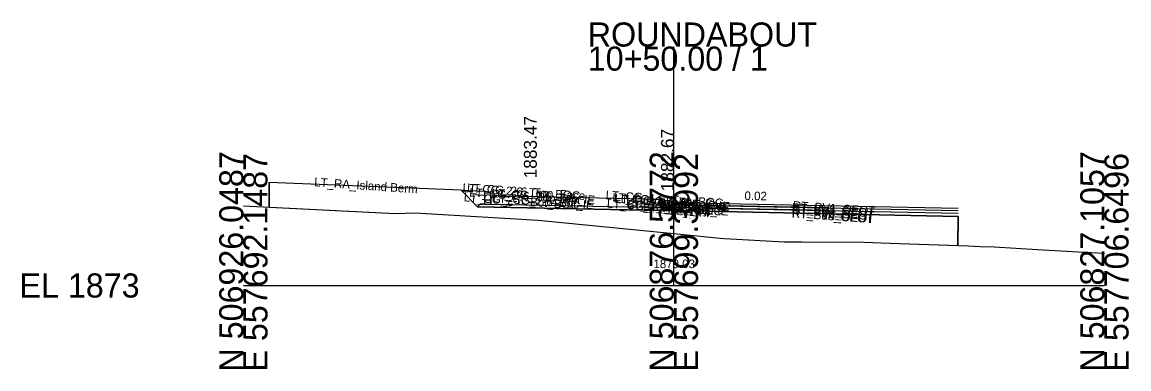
# Model space of a CAD drawing. Extents: x -36 to 140, y -10 to 2515.
# Drawn here: x -35.7 to 92.8, y 490.3 to 530.6 of the extents above; entities that cross this region are included whole.
import ezdxf

# ---------------------------------------------------------------- set-up
doc = ezdxf.new("R2010")
doc.units = 0
for name, color, linetype in [('Default', 7, 'Continuous'), ('Exist Cross Section Cell', 7, 'Continuous'), ('Exist XS Center Line Elevation Label', 7, 'Continuous'), ('Exist XS Ground Line', 7, 'Continuous'), ('Prop CMT Conc Surface', 7, 'Continuous'), ('Prop CMT Pvmt Course 1', 7, 'Continuous'), ('Prop CMT Pvmt Course 2', 7, 'Continuous'), ('Prop CMT Pvmt Course 3', 7, 'Continuous'), ('Prop CMT Pvmt Course 4', 7, 'Continuous'), ('Prop CMT Slope Grass', 7, 'Continuous'), ('Prop CMT Subgrade Earthwork', 7, 'Continuous'), ('Prop Conc 4in Sidewalk', 7, 'Continuous'), ('Prop XS Earthwork Shape', 7, 'Continuous'), ('Prop XS Finish Grade Earthwork', 7, 'Continuous'), ('Prop XS Hydro Elevations', 7, 'Continuous'), ('Typical Structure Recommendation Sheet 1 CELL', 7, 'Continuous')]:
    doc.layers.add(name, color=color, linetype=linetype)

msp = doc.modelspace()

# ---------------------------------------------------------------- linework, layer by layer
at = {"layer": 'Exist Cross Section Cell'}
for p, q in [((40, 500), (40, 527.77)), ((-10, 500), (40, 500)), ((40, 500), (90, 500))]:
    msp.add_line(p, q, dxfattribs=at)
at = {"layer": 'Exist XS Ground Line'}
msp.add_line((86.97, 503.93), (89.99, 503.75), dxfattribs=at)
msp.add_lwpolyline([(-10, 509.26), (7.68, 508.38), (9.93, 508.44), (24.23, 507.6), (40, 506.03), (45.36, 505.5), (45.89, 505.46), (52.81, 505.08), (54.85, 505.08), (62.09, 505.04), (65.08, 504.92), (74.19, 504.6), (75.57, 504.54), (77.2, 504.49), (82.21, 504.19), (86.97, 503.93), (90, 503.75)], dxfattribs=at)
at = {"layer": 'Prop CMT Conc Surface'}
for p, q in [((18.65, 510.75), (18, 510.96)), ((18, 510.96), (18, 509.96)), ((18.75, 509.96), (18.75, 510.61)), ((17.2, 509.16), (17.5, 509.46)), ((18, 509.46), (17.5, 509.46)), ((18, 509.96), (18.75, 509.96)), ((18, 509.96), (18, 509.46)), ((18, 509.46), (18.75, 509.46)), ((18.75, 509.46), (18.75, 509.96)), ((38.5, 509.05), (38.5, 510.05)), ((39.19, 509.82), (38.5, 510.05)), ((40, 509.05), (38.5, 509.05)), ((38.59, 509.26), (38.52, 509.25)), ((38.52, 509.25), (38.55, 509.14)), ((38.55, 509.14), (38.59, 509.26)), ((38.65, 509.88), (38.56, 509.88)), ((38.56, 509.88), (38.64, 509.79)), ((38.64, 509.79), (38.65, 509.88)), ((38.85, 509.58), (38.89, 509.43)), ((38.93, 509.52), (38.85, 509.58)), ((38.89, 509.43), (38.93, 509.52)), ((39.15, 509.29), (39.24, 509.24)), ((39.18, 509.16), (39.15, 509.29)), ((39.24, 509.24), (39.18, 509.16)), ((39.25, 509.73), (39.25, 509.73)), ((40, 509.64), (39.34, 509.64)), ((39.51, 509.25), (39.44, 509.23)), ((39.44, 509.23), (39.47, 509.12)), ((39.47, 509.12), (39.51, 509.25)), ((39.76, 509.56), (39.81, 509.41)), ((39.85, 509.5), (39.76, 509.56)), ((39.81, 509.41), (39.85, 509.5)), ((40, 509.64), (40, 509.05)), ((40, 509.05), (40, 509.63))]:
    msp.add_line(p, q, dxfattribs=at)
msp.add_lwpolyline([(40, 509.06), (40, 509.64)], dxfattribs=at)
msp.add_lwpolyline([(40, 509.06), (40, 509.64)], dxfattribs=at)
for centre in [(38.57, 509.64), (38.58, 509.53), (38.62, 509.16), (38.64, 509.37), (38.71, 509.97), (38.74, 509.68), (38.73, 509.52), (38.76, 509.12), (38.78, 509.39), (38.79, 509.29), (38.85, 509.63), (38.93, 509.78), (38.93, 509.36), (39.02, 509.5), (39.03, 509.1), (39.04, 509.23), (39.04, 509.64), (39.06, 509.8), (39.07, 509.36), (39.11, 509.55), (39.23, 509.57), (39.26, 509.47), (39.27, 509.1), (39.35, 509.24), (39.35, 509.08), (39.37, 509.55), (39.36, 509.32), (39.39, 509.52), (39.5, 509.52), (39.54, 509.15), (39.56, 509.36), (39.65, 509.5), (39.68, 509.11), (39.7, 509.37), (39.71, 509.28), (39.77, 509.62), (39.85, 509.34), (39.94, 509.48), (39.95, 509.09), (39.96, 509.21), (39.99, 509.34)]:
    msp.add_circle(centre, 0.00635, dxfattribs=at)
for centre, radius, start, end in [((18.6, 510.61), 0.146, 0, 71.5651), ((38.53, 509.06), 0.00635, 27.0386, 154.2416), ((39.16, 509.73), 0.0937, 0, 71.5651), ((39.34, 509.73), 0.0937, 180, 270)]:
    msp.add_arc(centre, radius, start, end, dxfattribs=at)
at = {"layer": 'Prop CMT Pvmt Course 1'}
for points in [[(40, 509.39), (40, 509.64)], [(40, 509.64), (73, 508.98)], [(40, 509.39), (40, 509.64)], [(40, 509.39), (40, 509.64)], [(58, 509.03), (40, 509.39)]]:
    msp.add_lwpolyline(points, dxfattribs=at)
at = {"layer": 'Prop CMT Pvmt Course 2'}
for points in [[(40, 509.05), (40, 509.39)], [(40, 509.06), (40, 509.39)], [(40, 509.39), (73, 508.73)], [(40, 509.06), (40, 509.39)], [(58, 508.7), (40, 509.06)]]:
    msp.add_lwpolyline(points, dxfattribs=at)
at = {"layer": 'Prop CMT Pvmt Course 3'}
msp.add_lwpolyline([(40, 509.06), (73, 508.4)], dxfattribs=at)
at = {"layer": 'Prop CMT Pvmt Course 4'}
msp.add_lwpolyline([(40, 508.72), (40, 508.72)], dxfattribs=at)
msp.add_lwpolyline([(40, 508.72), (40, 508.72)], dxfattribs=at)
msp.add_lwpolyline([(40, 508.72), (40, 508.72)], dxfattribs=at)
at = {"layer": 'Prop CMT Slope Grass'}
msp.add_line((-7, 509.11), (-7, 511.96), dxfattribs=at)
msp.add_lwpolyline([(15.29, 511.07), (-7, 511.96)], dxfattribs=at)
at = {"layer": 'Prop CMT Subgrade Earthwork'}
for p, q in [((17.2, 509.16), (15.29, 511.07)), ((17.2, 509.16), (38.5, 508.72)), ((38.5, 508.72), (39.99, 508.72)), ((39.99, 508.72), (73, 508.03)), ((73, 508.03), (72.98, 504.64))]:
    msp.add_line(p, q, dxfattribs=at)
at = {"layer": 'Prop Conc 4in Sidewalk'}
for p, q in [((18.75, 510.46), (18.75, 509.46)), ((18.75, 510.46), (38.5, 510.05)), ((18.75, 509.46), (38.5, 509.05))]:
    msp.add_line(p, q, dxfattribs=at)
at = {"layer": 'Prop XS Earthwork Shape'}
msp.add_lwpolyline([(24.23, 507.6), (40, 506.03), (45.36, 505.5), (45.89, 505.46), (52.81, 505.08), (54.85, 505.08), (62.09, 505.04), (65.08, 504.92), (72.98, 504.64), (73, 508.03), (39.99, 508.72), (38.5, 508.72), (17.2, 509.16), (15.29, 511.07), (-7, 511.96), (-7, 509.11), (7.68, 508.38), (9.93, 508.44)], close=True, dxfattribs=at)
at = {"layer": 'Prop XS Finish Grade Earthwork'}
msp.add_line((15.29, 511.07), (18, 510.96), dxfattribs=at)

# ---------------------------------------------------------------- texts
at = {"layer": 'Default'}
for p in [(0, 508.29), (0, 500)]:
    msp.add_text('-', height=0.0001, dxfattribs=at).set_placement(p)
at = {"layer": 'Exist Cross Section Cell'}
for s, p in [('ROUNDABOUT', (30, 527.77)), ('10+50.00 / 1', (30, 524.97)), ('EL 1873', (-36, 498.6))]:
    msp.add_text(s, height=2.8, dxfattribs=at).set_placement(p)
for s, p in [('N 506926.0487', (-10, 490)), ('N 506876.5772', (40, 490)), ('N 506827.1057', (90, 490)), ('E 557692.1487', (-7.2, 490)), ('E 557699.3992', (42.8, 490)), ('E 557706.6496', (92.8, 490))]:
    msp.add_text(s, height=2.8, rotation=90, dxfattribs=at).set_placement(p)
at = {"layer": 'Exist XS Center Line Elevation Label'}
msp.add_text('1879.03', height=1, dxfattribs=at).set_placement((37.62, 502.02))
at = {"layer": 'Prop XS Hydro Elevations'}
for s, height, rotation, p in [('1883.47', 1.5, 90, (24.08, 512.45)), ('1882.67', 1.5, 90, (40, 510.95)), ('0.02', 1, 358.8542, (48.19, 509.94))]:
    msp.add_text(s, height=height, rotation=rotation, dxfattribs=at).set_placement(p)
at = {"layer": 'Typical Structure Recommendation Sheet 1 CELL'}
for s, p in [('LT_RA_Island Berm', (-1.8, 511.54)), ('LT_CG_2-6_Top_BOC', (15.43, 510.87)), ('LT_CG_2-6_Top_Face', (15.95, 510.87)), ('LT_CG_2-6_Bot_BOC', (15.57, 509.79)), ('LT_CG_2-6_Top_Gut', (16.21, 510.35)), ('LT_CG_2-6_Top_IE', (18.8, 510.27)), ('LT_CG_2-6_Bot_IE', (18.94, 509.68)), ('LT_CG_1-6_Top_BOC', (32.05, 510.03)), ('LT_CG_1-6_Top_Face', (32.83, 509.78)), ('LT_CG_1-6_Top_Gut', (33.09, 509.6)), ('LT_CG_1-6_Top_IE', (34.43, 509.53)), ('LT_CG_1-6_Bot_BOC', (32.19, 509.05)), ('LT_CG_1-6_Bot_IE', (34.57, 508.94)), ('LT_MI_BOC', (35.04, 509.24)), ('LT_PV2_PGL', (36.36, 509.14)), ('LT_PV3_PGL', (36.36, 508.81)), ('LT_PV4_PGL', (36.36, 508.48)), ('LT_Sub_PGL', (36.38, 508.48)), ('RT_PV2_OEOT', (53.66, 508.58)), ('RT_PV3_OEOT', (53.66, 508.25)), ('RT_PV1_OEOT', (53.78, 508.82)), ('RT_PV4_OEOT', (53.66, 507.92)), ('RT_Sub_OEOT', (53.69, 507.91))]:
    msp.add_text(s, height=1, rotation=356, dxfattribs=at).set_placement(p)

doc.saveas('drawing.dxf')
